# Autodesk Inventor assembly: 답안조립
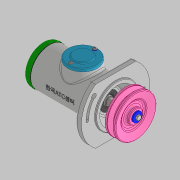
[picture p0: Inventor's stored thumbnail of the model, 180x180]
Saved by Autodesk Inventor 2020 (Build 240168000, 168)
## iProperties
Created: 2022-05
Part Number: 답안조립
Document SubType Name: Assembly
Designer: User
Author: User
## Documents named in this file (22)
- C:\Users\User\Desktop\720506V1037\답안조립.iam
- C:\Users\User\Desktop\720506V1037\본체.ipt
- C:\Users\User\Desktop\720506V1037\V-벨트풀리.ipt
- C:\Users\User\Desktop\720506V1037\개스킷.ipt
- C:\Users\User\Desktop\720506V1037\너트 M10.ipt
- C:\Users\User\Desktop\720506V1037\멈춤나사 M3.ipt
- C:\Users\User\Desktop\720506V1037\멈춤링 15 x 1.ipt
- C:\Users\User\Desktop\720506V1037\멈춤링 35 x 1.6.ipt
- C:\Users\User\Desktop\720506V1037\베어링 6202.ipt
- C:\Users\User\Desktop\720506V1037\볼트 M4 x 10.ipt
- C:\Users\User\Desktop\720506V1037\부시1.ipt
- C:\Users\User\Desktop\720506V1037\부시2.ipt
- C:\Users\User\Desktop\720506V1037\사이드 커버.ipt
- 사이드 커버.ipt
- C:\Users\User\Desktop\720506V1037\십자볼트 M3 x 10.ipt
- C:\Users\User\Desktop\720506V1037\오일 실 15 x 30 x 7.ipt
- C:\Users\User\Desktop\720506V1037\와셔 3 x 6.ipt
- C:\Users\User\Desktop\720506V1037\와셔 4 x 16.ipt
- C:\Users\User\Desktop\720506V1037\와셔 10 x 21.ipt
- C:\Users\User\Desktop\720506V1037\축.ipt
- C:\Users\User\Desktop\720506V1037\키 4 x 4.ipt
- C:\Users\User\Desktop\720506V1037\탑 커버.ipt
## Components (3 placed, 3 different names)
1. V-벨트풀리:1
2. 개스킷:1
3. ISO 4017 M4 x 10:1 — 각도:3, 각도:4, 각도:6, 각도:7
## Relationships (4: Angle 4)
- 각도:3 [Angle]: ISO 4017 M4 x 10:1
- 각도:4 [Angle]: ISO 4017 M4 x 10:1
- 각도:6 [Angle]: ISO 4017 M4 x 10:1
- 각도:7 [Angle]: ISO 4017 M4 x 10:1
